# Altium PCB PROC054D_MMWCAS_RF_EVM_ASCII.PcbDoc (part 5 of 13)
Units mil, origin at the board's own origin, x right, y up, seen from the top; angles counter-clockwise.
Board outline 6299.21 x 5370.07 mil, 8 copper layers (L1 TOP, L2 GND, L3 SIGNAL 1, L4 GND, L5 SIGNAL 2, L6 SIGNAL 3, L7 GND, L8 BOTTOM), stack 53.5 mil thick; 775 components, 552 nets, 2648 pads, 7845 vias.
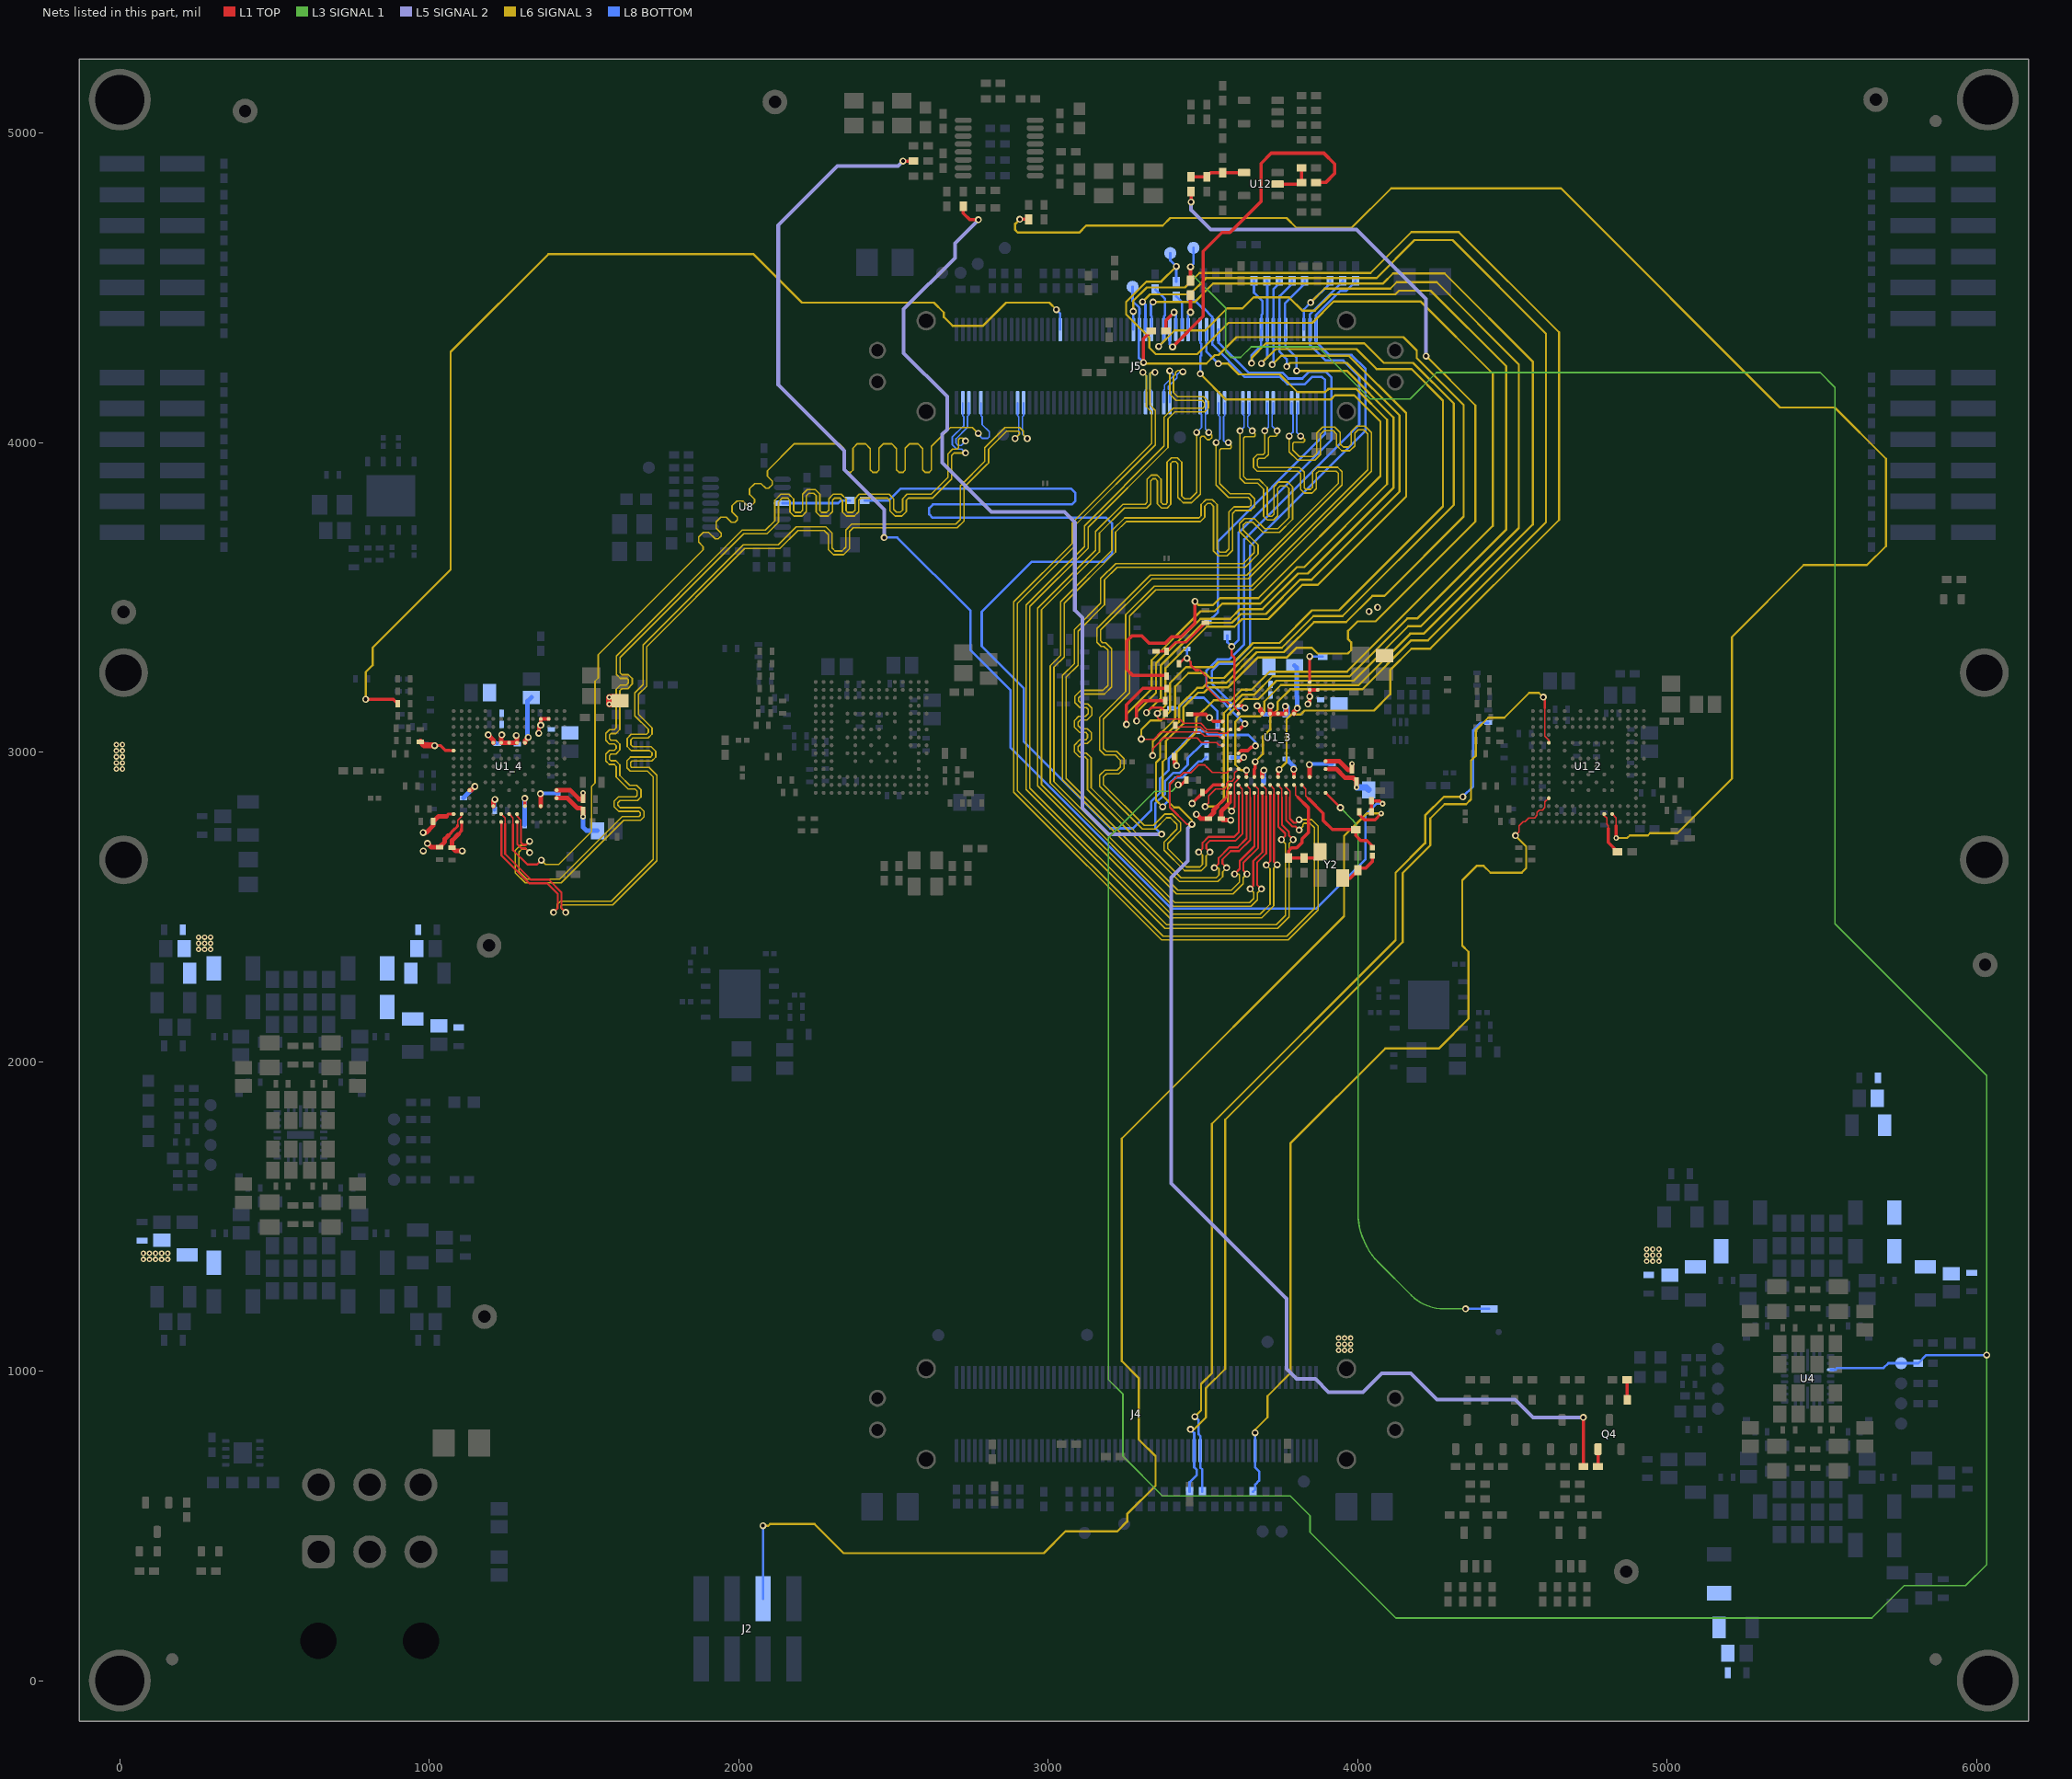
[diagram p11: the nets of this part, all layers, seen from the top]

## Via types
v1: diameter 15.74, hole 5.9, L1 TOP to L2 GND, tented both sides, 5522 vias
v2: diameter 22.4, hole 12.2, L1 TOP to L8 BOTTOM, tented both sides, 1522 vias
v3: diameter 18, hole 8, L1 TOP to L8 BOTTOM, tented both sides, 727 vias
v4: diameter 18, hole 7.87, L1 TOP to L8 BOTTOM, tented top, 50 vias
v5: diameter 24, hole 12, L1 TOP to L8 BOTTOM, tented both sides, 13 vias
v6: diameter 19.68, hole 7.87, L1 TOP to L8 BOTTOM, tented top, 10 vias
v7: diameter 15.74, hole 5.9, L1 TOP to L2 GND, tented top, 1 vias

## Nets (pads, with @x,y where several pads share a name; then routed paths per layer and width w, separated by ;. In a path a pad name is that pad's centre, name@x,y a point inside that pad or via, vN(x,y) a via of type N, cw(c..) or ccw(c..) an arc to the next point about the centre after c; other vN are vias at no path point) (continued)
AWR_2_UART_RX: J4.100 R179_2.1 U1_2.N5 | length 3336.1
  L1 TOP w4: 4605,3142.12 4605,3051 4606,3050 4606,3049.9 4617.94,3037.96 U1_2.N5@4617.94,3030.27
  L1 TOP w8: v2(4600,3177.36) 4605,3172.36 4605,3142.12
  L6 SIGNAL 3 w6.9: v2(3460,812) 3472,812 3509.9,849.9 3509.9,945.07 3571.9,1007.07 3571.9,1812.47 4145.41,2385.97 4145.41,2608.91 4235.1,2698.6 4235.1,2785.63 4280.89,2831.42 4350.77,2831.42 4366.51,2847.16 4366.51,2972.86 4381.71,2988.06 4381.71,3070.64 4422.44,3111.36 4474.45,3111.36 4554.59,3191.51 4585.85,3191.51 v2(4600,3177.36)
  L8 BOTTOM w7.75: R179_2.1@3457,610.42 3457,641.1 3479.46,663.56 3479.46,681.54 3471.93,689.07 3471.93,800.07 v2(3460,812)
AWR_2_UART_TX: J4.101 R11_2.1 R178_2.1 | length 2937.4
  L6 SIGNAL 3 w6.9: v2(3474,853) 3494.15,873.15 3494.15,958.34 3528.87,993.06 3528.87,1798.87 4122.88,2392.87 4122.88,2610.47 4218.18,2705.77 4218.18,2795.22 4278.49,2855.54 v2(4339.79,2855.54)
  L8 BOTTOM w7.75: v2(3474,853) 3486,841 3486,796 3491.61,790.39 3491.61,688.74 3498,682.35 R178_2.1@3498,610.42 ; v2(4339.79,2855.54) 4373.35,2889.1 4373.35,3070.72 4397.63,3095 R11_2.1@4422.06,3095
AWR_2_WARM_RST: J4.110 R174_2.1 U1_2.N12 | length 2930.5
  L1 TOP w4: v2(4510,2730) 4522,2742 4522,2762 4535,2775 4541,2775 4553.46,2787.46 4571.94,2787.46 4579.85,2795.37 4579.85,2805.14 4587.17,2812.46 4596.94,2812.46 4605.44,2820.96 4605.44,2838.64 U1_2.N12@4617.94,2851.13
  L6 SIGNAL 3 w6.9: v2(3668.78,801) 3668.78,810.73 3708.84,850.79 3708.84,919.47 3782.81,993.44 3782.81,1736.06 4088.99,2042.24 4262.01,2042.24 4358.04,2138.27 4358.04,2354.55 4338.18,2374.4 4338.18,2586.12 4384.3,2632.24 4407.51,2632.24 4429.42,2610.34 4530.22,2610.34 4544.96,2625.08 4544.96,2695.04 v2(4510,2730)
  L8 BOTTOM w7.75: R174_2.1@3662,610.42 3668.78,617.2 3668.78,633.76 3681.55,646.53 3681.55,675.72 3668.78,688.49 v2(3668.78,801)
AWR_2_XTAL_CLKM: R129.2 U1_2.F14 | length 139.7
  L1 TOP w4: U1_2.F14@4797.07,2799.95 4797.07,2794.92 4805,2786.99 4805,2767.1 4809.68,2762.42 4809.68,2752.33
  L1 TOP w10.5: 4809.68,2752.33 4809.68,2708.42 R129.2@4840.01,2678.08
AWR_2_XTAL_CLKP: R104.2 U1_2.E14 | length 5230.2
  L1 TOP w4: U1_2.E14@4822.67,2799.95 4835.37,2787.25 4835.37,2762.23
  L1 TOP w10.5: v2(2908.09,4721.32) R104.2@2936.49,4721.32 ; v3(4835.37,2722.31) 4835.37,2762.23
  L6 SIGNAL 3 w6.9: v2(2908.09,4721.32) 2893.5,4706.73 2893.5,4686.9 2901.88,4678.51 3100.48,4678.51 3122.83,4700.86 3369.77,4700.86 3394.77,4725.86 3770.26,4725.86 3802.31,4693.81 3980.44,4693.81 4108.32,4821.69 4657.41,4821.69 5365.44,4113.65 5541.51,4113.65 5707.57,3947.59 5707.57,3665.65 5646.12,3604.2 5441.75,3604.2 5209.7,3372.15 5209.7,2914.51 5033.49,2738.29 4945.21,2738.29 4937.88,2730.96 4879.58,2730.96 4870.93,2722.31 v3(4835.37,2722.31)
AWR_3_1V0_RF1_FILT: C87.1 C88.1 C91.1 C136_3.1 C137_3.1 C138_3.1 C139_3.1 L23.2 U1_3.G5 U1_3.H5 U1_3.J5 | length 127.1
  L1 TOP w15: v2(3719.09,3149.57) 3717.3,3147.78 U1_3.J5@3717.3,3124.27 U1_3.G5@3768.48,3124.27 3768.48,3140.51 3766.34,3142.65 v2(3766.34,3147.83)
  L8 BOTTOM w22: v2(3766.34,3147.83) 3769.38,3144.79 C136_3.1@3769.38,3123.65
AWR_3_1V0_RF2_FILT: C93.1 C140_3.1 C141_3.1 C204.1 C207.1 L24.2 R188_3.2 U1_3.C2 U1_3.D2 | length 74.2
  L1 TOP w12: v2(3839,3155) 3845.25,3161.25 U1_3.D2@3845.26,3201.04 U1_3.C2@3870.85,3201.04
  other v2: 3845.24,3179.65 4037.03,3454.24 4064.35,3467.78
AWR_3_1V2_FILT: C142_3.1 C143_3.1 C144_3.1 C145_3.1 C146_3.1 C147_3.1 C154.1 C155.1 C156.1 L19.2 U1_3.F13 U1_3.N11 U1_3.P14 U1_3.P15 U1_3.R6 U1_3.R14 | length 678.8
  L1 TOP w4: 3576.5,2857.69 3576.5,2873.5 3589.35,2886.35 U1_3.P14@3589.35,2893.95
  L1 TOP w8: 3568.43,2846.28 3576.5,2854.35 3576.5,2857.69 ; 3589.35,2845.01 U1_3.P15@3589.35,2868.36
  L1 TOP w10: v2(3465,2834) 3498.58,2867.58 C146_3.1@3498.58,2870 3509.97,2870 3533.93,2893.96 U1_3.R14@3563.76,2893.95 ; v2(3521.08,3111.07) 3533.48,3098.68 U1_3.R6@3563.76,3098.68 ; 3545.75,2823.6 3568.43,2846.28 ; 3579.25,2828.86 3589.35,2838.95 3589.35,2845.01 ; U1_3.N11@3614.94,2970.72 3620.02,2970.73 v2(3632.19,2982.9)
  L1 TOP w12: C142_3.1@3457.49,3122.71 3509.45,3122.71 v2(3521.08,3111.07) ; v2(3793.51,2944.72) 3793.51,2937.18 3794.07,2936.62 U1_3.F13@3794.07,2919.55
  L1 TOP w15: v2(3479,2798.99) 3492.42,2785.57 C147_3.1@3518,2785.58 ; C147_3.1@3518,2787 3535,2804 3535,2812.85 3545.75,2823.6 ; 3579.25,2828.86 3559,2808.6 C143_3.1@3559,2785.58 3564.59,2779.99 v2(3590,2779.99)
  L8 BOTTOM w12: C145_3.1@3595.75,2982.9 v2(3632.19,2982.9)
  L8 BOTTOM w15: C144_3.1@3769.06,2978.27 3793.51,2953.82 v2(3793.51,2944.72)
  other v3: 3938.25,1067.33 3957.94,1067.33 3977.62,1067.33 3938.25,1087.02 3957.94,1087.02 3977.62,1087.02 3938.25,1106.7 3957.94,1106.7 3977.62,1106.7
AWR_3_1V8_FILT: C128_3.1 C129_3.1 C130_3.1 C131_3.1 C132_3.1 C133_3.1 C134_3.1 C135_3.1 C158.1 C159.1 C160.1 L22.2 U1_3.B11 U1_3.B12 U1_3.D13 U1_3.F5 U1_3.K5 U1_3.K13 | length 707.4
  L1 TOP w12: U1_3.B12@3896.44,2945.13 3905.67,2945.13
  L1 TOP w15: v2(3675.39,3149.45) 3686.19,3138.65 3686.19,3132.45 3691.71,3126.93 U1_3.K5@3691.71,3124.27 ; U1_3.K13@3691.71,2919.55 3691.71,2935.82 v2(3697.03,2941.14) ; U1_3.F5@3794.07,3124.27 3794.07,3130.78 v2(3804.99,3141.7) ; v2(3844,2959.6) 3845.25,2958.35 U1_3.D13@3845.25,2919.55 ; U1_3.B11@3896.44,2970.72 3940.64,2970.72 3969.35,2942.02 C132_3.1@3981.84,2942.02 v3(3981.84,2962.39) ; 3905.67,2945.13 3931.49,2945.13 3959.9,2916.72 3986.18,2916.72 C131_3.1@3996.84,2906.06 v3(3996.84,2885.69)
  L8 BOTTOM w12: v2(3844,2959.6) 3846.4,2962 C134_3.1@3918.09,2962
  L8 BOTTOM w15: v2(3675.39,3149.45) 3703.15,3121.69 C128_3.1@3704.89,3121.69 ; C135_3.1@3696.3,2906 3696.3,2940.41 v2(3697.03,2941.14) ; C130_3.1@3796.42,3279.39 3802.72,3273.09 C129_3.1@3802.72,3216.01 3802.72,3182.09 3804.99,3179.82 v2(3804.99,3141.7)
  L8 BOTTOM w20: v3(3996.84,2885.69) 4028.07,2885.69 C133_3.1@4035.5,2878.26
  other v3: 4934.19,1354.8 4953.87,1354.8 4973.56,1354.8 4934.19,1374.48 4953.87,1374.48 4973.56,1374.48 4934.19,1394.17 4953.87,1394.17 4973.56,1394.17
AWR_3_BSS_LOGGER: J5.41 R14_3.1 | length 2321.9
  L1 TOP w10.5: R14_3.1@3385.09,3246 3382.69,3248.4 3272.6,3248.4 3254,3267 3254,3358.89 3270.08,3374.97 3303.03,3374.97 3326.71,3351.29 3377.1,3351.29 3398.81,3373 3430,3373 3474.73,3417.73 v2(3474.73,3487.05)
  L6 SIGNAL 3 w6.9: v2(3474.73,3487.05) 3487.02,3474.76 3532.33,3474.76 3555.14,3497.57 3679.24,3497.57 4073.72,3892.06 4073.72,4068.11 3988.9,4152.93 3926.62,4152.93 3912.78,4139.09 3574.52,4139.09 v2(3491.61,4222)
  L8 BOTTOM w7.75: v2(3491.61,4222) 3491.61,4278.61 3495,4282 3495,4319 3491.61,4322.39 J5.41@3491.61,4365.06
AWR_3_CSI2_CLK_N: J5.101 U1_3.J14 | length 3367.5
  L1 TOP w4: U1_3.J14@3717.3,2893.95 3729.89,2881.36 3729.89,2862.67
  L1 TOP w6.5: 3729.89,2862.67 3729.89,2646.1 v2(3740,2635.99)
  L6 SIGNAL 3 w5: v2(3479.61,4033) 3479.61,3838.77 3458.84,3818 3440.98,3818 3431.49,3827.49 3431.49,3936.59 3417.53,3950.56 3397.89,3950.56 3384.24,3936.91 3384.24,3805.24 3380,3801 3371.21,3801 3364.99,3807.22 3364.99,3881.76 3351.75,3895 3332.98,3895 3319.74,3881.76 3319.74,3807.21 3313.53,3801 3241.63,3801 3153.51,3712.88 3153.51,3652.05 2966.23,3464.78 2966.23,2891.06 3392.4,2464.89 3690.12,2464.89 3729,2503.77 3729,2624.99 ; 3729,2625 v2(3740,2635.99) 3729,2624.99
  L8 BOTTOM w5.25: v2(3479.61,4033) 3496,4049.39 3496,4090.01 3491.61,4094.4 J5.101@3491.61,4128.84
AWR_3_CSI2_CLK_P: J5.102 U1_3.J15 | length 3330.6
  L1 TOP w6.5: v2(3705,2634.99) 3717.89,2647.88 3717.89,2867.77 U1_3.J15@3717.3,2868.36
  L6 SIGNAL 3 w5: v2(3519,4033) 3528.89,4023.11 3528.89,4016.33 3521.8,4009.24 3514.43,4009.24 3503.47,4020.2 3496.02,4020.2 3491.61,4015.79 3491.61,3833.8 3463.81,3806 3436.01,3806 3419.49,3822.52 3419.49,3931.62 3412.56,3938.56 3402.86,3938.56 3396.24,3931.94 3396.24,3800.27 3384.97,3789 3366.24,3789 3352.99,3802.25 3352.99,3876.79 3346.78,3883 3337.95,3883 3331.74,3876.79 3331.74,3802.24 3318.5,3789 3246.6,3789 3165.51,3707.91 3165.51,3647.08 2978.23,3459.81 2978.23,2896.03 3397.38,2476.89 3685.15,2476.89 3717,2508.74 3717,2623 v2(3705,2634.99)
  L8 BOTTOM w5.25: J5.102@3511.3,4128.84 3511.3,4094.3 3508,4091 3508,4044 v2(3519,4033)
AWR_3_CSI2_TX0_N: J5.92 U1_3.G14 | length 3373.1
  L1 TOP w4: U1_3.G14@3768.48,2893.95 3768.48,2886.51 3781.07,2873.92 3781.07,2853.99
  L1 TOP w6.5: 3781.07,2853.99 3781.07,2784.92 3794.35,2771.64 3800.85,2771.64 v2(3811,2781.79)
  L6 SIGNAL 3 w5: v2(3306,4227) 3317.21,4215.79 3317.21,4116.44 3334.53,4099.11 3334.53,3997.27 3078,3740.74 3078,3674.44 2888.71,3485.15 2888.71,2870.62 3366.21,2393.11 3775.75,2393.11 3872.33,2489.69 3872.33,2760.91 3851.44,2781.8 v2(3811,2781.79)
  L8 BOTTOM w5.25: v2(3306,4227) 3317,4216 3317,4172.22 3314.45,4169.67 J5.92@3314.45,4128.84
AWR_3_CSI2_TX0_P: J5.93 U1_3.G15 | length 3336.4
  L1 TOP w6.5: U1_3.G15@3768.48,2868.36 3769.07,2867.77 3769.07,2779.94 3789.37,2759.64 3799.35,2759.64 v2(3811,2747.99)
  L6 SIGNAL 3 w5: v2(3345.39,4227) 3332.54,4227 3329.21,4223.66 3329.21,4121.41 3346.53,4104.09 3346.53,3992.3 3090,3735.77 3090,3669.47 2900.71,3480.18 2900.71,2875.59 3371.18,2405.11 3770.78,2405.11 3860.33,2494.66 3860.33,2755.94 3846.47,2769.8 3826.79,2769.8 3823.26,2766.27 3823.26,2760.26 v2(3811,2747.99)
  L8 BOTTOM w5.25: J5.93@3334.13,4128.84 3334.13,4168.26 3329,4173.39 3329,4223.46 3332.54,4227 v2(3345.39,4227)
AWR_3_CSI2_TX1_N: J5.95 U1_3.H14 | length 3368.1
  L1 TOP w4: U1_3.H14@3742.89,2893.95 3755.48,2881.36 3755.48,2853.99
  L1 TOP w6.5: 3755.48,2853.99 3755.48,2764.73 3778.01,2742.21 3778.01,2730.67 v2(3791.4,2717.28)
  L6 SIGNAL 3 w5: v2(3393,4232) 3393,4157 3413.53,4136.47 3497.61,4136.47 3505.69,4128.38 3505.69,4116.9 3500.28,4111.49 3404.37,4111.49 3374.97,4082.09 3374.97,3989.13 3117,3731.16 3117,3663.88 2928.7,3475.59 2928.7,2879.14 3377.74,2430.1 3741.81,2430.1 3779,2467.28 3779,2704.87 v2(3791.4,2717.28)
  L8 BOTTOM w5.25: J5.95@3373.5,4128.84 3373.51,4169.81 3376.06,4172.36 3376.06,4186.23 3404.26,4214.43 3404.26,4220.74 v2(3393,4232)
AWR_3_CSI2_TX1_P: J5.96 U1_3.H15 | length 3328.5
  L1 TOP w6.5: U1_3.H15@3742.89,2868.36 3743.48,2867.77 3743.48,2759.75 3766,2737.23 3766,2730.67 ; v2(3754,2717.28) 3766,2729.28
  L6 SIGNAL 3 w5: v2(3435.39,4229) 3431.16,4233.22 3418.37,4233.22 3412.05,4226.9 3412.05,4220.03 3405,4212.98 3405,4161.97 3418.5,4148.47 3502.58,4148.47 3517.69,4133.36 3517.69,4111.93 3505.25,4099.49 3409.34,4099.49 3386.97,4077.12 3386.97,3984.16 3129,3726.19 3129,3658.91 2940.7,3470.62 2940.7,2884.11 3382.71,2442.1 3736.84,2442.1 3767,2472.25 3767,2704.28 v2(3754,2717.28)
  L8 BOTTOM w5.25: J5.96@3393.19,4128.84 3393.19,4167.6 3388.06,4172.73 3388.06,4181.26 3416.26,4209.46 3416.26,4219.35 3425.91,4229 v2(3435.39,4229)
AWR_3_CSI2_TX2_N: J5.104 U1_3.K14 | length 3362.1
  L1 TOP w4: U1_3.K14@3691.71,2893.95 3704.3,2881.36 3704.3,2857.99
  L1 TOP w6.5: v2(3688.96,2557.99) 3675,2571.95 3675,2642.99 3704.3,2672.29 3704.3,2857.99
  L6 SIGNAL 3 w5: v2(3542.61,4000) 3542.61,3862.76 3582.75,3822.62 3646.18,3822.62 3655.4,3813.41 3655.4,3798.04 3649.73,3792.37 3600.36,3792.37 3584,3776.01 3584,3656.87 3573.52,3646.4 3555.18,3646.4 3546,3655.57 3546,3799.96 3530.26,3815.7 3510.15,3815.7 3494.1,3799.65 3494.1,3764.08 3487.02,3757 3247.25,3757 3205.83,3715.57 3205.83,3651.69 3039.78,3485.65 3039.78,3312.51 3006.51,3279.24 3006.51,2899.91 3404.5,2501.91 3655.84,2501.91 3676.34,2522.42 3676.34,2545.38 v2(3688.96,2557.99)
  L8 BOTTOM w5.25: v2(3542.61,4000) 3555,4012.39 3555,4083.99 3550.67,4088.32 J5.104@3550.67,4128.84
AWR_3_CSI2_TX2_P: J5.105 U1_3.K15 | length 3332.1
  L1 TOP w6.5: v2(3652.56,2557.99) 3663,2568.43 3663,2647.97 3692.3,2677.27 3692.3,2867.77 U1_3.K15@3691.71,2868.36
  L6 SIGNAL 3 w5: v2(3582,4000) 3591.34,3990.66 3591.34,3984.02 3588.02,3980.7 3559.16,3980.7 3554.61,3976.15 3554.61,3867.73 3587.72,3834.62 3651.15,3834.62 3667.4,3818.38 3667.4,3793.07 3654.7,3780.37 3605.33,3780.37 3596,3771.04 3596,3651.9 3578.49,3634.4 3550.21,3634.4 3534,3650.6 3534,3794.99 3525.29,3803.7 3515.12,3803.7 3506.1,3794.68 3506.1,3759.11 3491.99,3745 3252.23,3745 3217.83,3710.59 3217.83,3646.71 3051.78,3480.67 3051.78,3307.54 3018.51,3274.27 3018.51,2904.88 3409.47,2513.91 3650.87,2513.91 3664.34,2527.39 3664.34,2546.22 v2(3652.56,2557.99)
  L8 BOTTOM w5.25: J5.105@3570.35,4128.84 3570.35,4087.34 3567,4083.99 3567,4005.57 3569.78,4002.79 3579.21,4002.79 v2(3582,4000)
AWR_3_CSI2_TX3_N: J5.108 U1_3.L14 | length 3356.6
  L1 TOP w4: U1_3.L14@3666.12,2893.95 3678.71,2881.36 3678.71,2859.99
  L1 TOP w6.5: v2(3642.4,2605.99) 3631,2617.39 3631,2642.99 3678.71,2690.7 3678.71,2859.99
  L6 SIGNAL 3 w5: v2(3620,4038) 3620,3885.7 3636.44,3869.27 3676.76,3869.27 3696.24,3849.79 3696.24,3762.06 3708.08,3750.22 3727.93,3750.22 3741.49,3763.78 3741.49,3852.07 3749.95,3860.52 3769.23,3860.52 3778,3851.76 3778,3757.52 3742.07,3721.6 3699.77,3721.6 3666.57,3754.8 3634.65,3754.8 3618.19,3738.35 3618.19,3712.47 3666.2,3664.46 3666.2,3644.66 3630.75,3609.21 3218.03,3609.21 3169.81,3560.99 3169.81,3481.08 3084.43,3395.7 3084.43,3285.75 3046.35,3247.68 3046.35,2910.31 3414.47,2542.18 3597.18,2542.18 3630,2575 3630,2593.6 v2(3642.4,2605.99)
  L8 BOTTOM w5.25: v2(3620,4038) 3621,4038 3633,4050 3633,4087 3629.41,4090.59 J5.108@3629.41,4128.84
AWR_3_CSI2_TX3_P: J5.109 U1_3.L15 | length 3334.2
  L1 TOP w6.5: v2(3602.2,2605.99) 3619,2622.79 3619,2647.97 3666.71,2695.68 3666.71,2867.77 U1_3.L15@3666.12,2868.36
  L6 SIGNAL 3 w5: v2(3602.2,2605.99) 3614.86,2606 3618,2602.86 3618,2579.98 3592.2,2554.18 3419.45,2554.18 3058.35,2915.29 3058.35,3242.71 3096.43,3280.78 3096.43,3390.73 3181.81,3476.11 3181.81,3556.02 3223,3597.21 3635.72,3597.21 3678.2,3639.69 3678.2,3669.44 3630.19,3717.44 3630.19,3733.38 3639.62,3742.8 3661.6,3742.8 3694.8,3709.6 3747.04,3709.6 3790,3752.55 3790,3856.73 3774.2,3872.52 3744.98,3872.52 3729.49,3857.04 3729.49,3768.75 3722.96,3762.22 3713.05,3762.22 3708.24,3767.03 3708.24,3854.76 3681.73,3881.27 3641.41,3881.27 3632,3890.68 3632,4014.25 3636.42,4018.67 3665.39,4018.67 3668.64,4021.92 3668.64,4028.75 v2(3659.39,4038)
  L8 BOTTOM w5.25: J5.109@3649.09,4128.84 3650,4127.93 3650,4089 3645,4084 3645,4052.39 v2(3659.39,4038)
AWR_3_DIG_SYNCIN: R134.2 R185_3.2 U1_3.N10 | length 4055.5
  L1 TOP w10.5: U1_3.N10@3614.94,2996.31 3623.48,3004.85 3644.69,3004.85 3655.16,3015.32 3664.77,3015.32 v2(3669.59,3020.14)
  L8 BOTTOM w7.75: R134.2@2406.54,3813.05 2485.5,3813.05 2523.92,3851.47 3073.92,3851.47 3087.39,3837.99 3087.39,3810.8 3076.84,3800.24 2627.43,3800.24 2615.41,3788.22 2615.41,3768.72 2626.89,3757.25 3187.8,3757.25 3206.05,3738.99 3206.05,3641.46 3179.08,3614.49 2946.04,3614.49 2785.15,3453.59 2785.15,3342.4 2920.89,3206.66 2920.89,3034.08 3201.19,2753.78 3274.73,2753.78 3332.87,2811.91 3332.87,2840.39 3361.14,2868.66 3361.14,2914.18 3389.62,2942.67 3389.62,2979.17 3476.99,3066.54 R185_3.2@3482.96,3066.54 3507.45,3066.54 3518.63,3055.36 3646.87,3055.36 3669.59,3032.65 v2(3669.59,3020.14)
AWR_3_DIG_SYNCIN_RS: R134.1 U8.12 | length 221.8
  L8 BOTTOM w7.75: U8.12@2141.18,3804.18 2321.49,3804.18 2330.36,3813.05 R134.1@2359.3,3813.05
AWR_3_DIG_SYNCOUT: R1_3.1 R157.1 TP1_3.1 | length 3695.6
  L1 TOP w10.5: R1_3.1@3406.9,2985 3406.9,2964.1 v2(3415,2956)
  L6 SIGNAL 3 w6.9: v2(3414,4569.13) 3365.18,4520.31 3317.76,4520.31 3251.71,4454.26 3251.71,4414.13 3326.89,4338.95 3326.89,4306.54 3347.77,4285.66 3481.8,4285.66 3582.85,4386.71 3853.45,4386.71 3923.02,4456.27 4203.36,4456.27 4437.13,4222.49 4437.13,3731.13 3965.58,3259.58 3715.28,3259.58 3657.01,3201.31 3624.36,3201.31 3590.29,3167.23 3535.06,3167.23 3478.11,3110.28 3478.11,3063.91 3415,3000.8 v2(3415,2956)
  L8 BOTTOM w7.75: TP1_3.1@3394.61,4611.81 3394.61,4588.52 v2(3414,4569.13) R157.1@3414,4519.67
AWR_3_FMCW_CLKOUT: J3.1 U1_3.B15 | length 1988.6
  L1 TOP w8.4: U1_3.B15@3896.44,2868.36 v5(3943.9,2820.9)
  L3 SIGNAL 1 w5: v5@3944.09,2820.9 v5(3943.9,2820.9) 3983.22,2781.58 cw(c3939.64,2737.99) 4001.28,2737.99 4001.28,1512.06 ccw(c4230.17,1512.06) 4068.32,1350.21 4173.32,1245.21 ccw(c4279.63,1351.52) 4279.63,1201.17 v2(4349.11,1201.17)
  L8 BOTTOM w7.75: v2(4349.11,1201.17) J3.1@4424.63,1201.17
AWR_3_FMCW_SYNCOUT: R83.1 U1_3.D1 | length 123.8
  L1 TOP w8.4: U1_3.D1@3845.26,3226.63 v2(3845.26,3309)
  L8 BOTTOM w7.75: v2@3845.26,3308.75 R83.1@3886.65,3308.75
AWR_3_GPIO_0: J5.60 R16_3.2 U1_3.N4 | length 1868.9
  L1 TOP w10.5: U1_3.N4@3614.94,3149.86 3628.82,3149.86 v2(3635.99,3142.69)
  L8 BOTTOM w7.75: v2(3635.99,3142.69) 3607.02,3142.69 3528.56,3221.15 3528.56,3261.66 3552.6,3285.7 3596.09,3285.7 3652.58,3342.19 3652.58,3666.6 4025.73,4039.75 4025.73,4237.57 3980.56,4282.74 3909.26,4282.74 3865.63,4326.37 J5.60@3865.63,4365.06 3865.63,4411.67 3944.88,4490.92 3963.46,4490.92 3993,4520.45 R16_3.2@3993,4523
AWR_3_GPIO_1: J5.59 R17_3.2 U1_3.N7 | length 1880.7
  L1 TOP w10.5: U1_3.N7@3614.94,3073.09 3617.38,3073.09 v2(3635.69,3091.4)
  L8 BOTTOM w7.75: v2(3635.69,3091.4) 3511.59,3215.5 3511.59,3263.43 3547.54,3299.38 3584.57,3299.38 3633.58,3348.39 3633.58,3686.92 4005.42,4058.76 4005.42,4213.12 3953.16,4265.37 3896.63,4265.37 3846,4316 3846,4365 J5.59@3845.94,4365.06 3845.94,4414.41 3952,4520.46 R17_3.2@3952,4523
AWR_3_GPIO_2: J5.58 R18_3.2 U1_3.N13 | length 3153.9
  L1 TOP w4: 3602.44,2863 3602.44,2900.5 3614.94,2913 U1_3.N13@3614.94,2919.55
  L1 TOP w6: v2@3593,2816 3596.44,2816 3602.44,2822 3602.44,2863
  L6 SIGNAL 3 w6.9: v2(3593,2809) 3580.14,2821.86 3580.14,3119.16 3632.51,3171.53 3678.83,3171.53 3738.08,3230.78 3987.64,3230.78 4163.73,3406.87 4204.28,3406.87 4521.16,3723.75 4521.16,4252.6 4255.68,4518.08 4126.56,4518.08 4105.91,4497.43 3893.06,4497.43 v2(3847.92,4452.29)
  L8 BOTTOM w7.75: J5.58@3826.26,4365.06 3826.26,4430.63 v2(3847.92,4452.29) 3911,4515.37 R18_3.2@3911,4523
AWR_3_LVDS_FRCLK_N: J5.112 U1_3.M14 | length 3354.6
  L1 TOP w4: U1_3.M14@3640.53,2893.95 3653.12,2881.36 3653.12,2852.99
  L1 TOP w6.5: v2(3576.62,2625.99) 3563,2639.61 3563,2652.99 3590,2679.99 3616.98,2679.99 3653.12,2716.13 3653.12,2852.99
  L6 SIGNAL 3 w5: v2(3576.62,2625.99) 3564,2613.38 3564,2597.91 3548.09,2582 3424.15,2582 3126.83,2879.32 3126.83,2976.49 3118.69,2984.63 3100.19,2984.63 3084.48,3000.33 3084.48,3022.25 3102.04,3039.8 3121.46,3039.8 3127.24,3045.58 3127.24,3057.8 3121.39,3063.65 3101.62,3063.65 3084.41,3080.86 3084.41,3101.64 3098.22,3115.45 3120.39,3115.45 3129.17,3124.23 3129.17,3137.79 3123.08,3143.87 3103.02,3143.87 3086.27,3160.62 3086.27,3180.24 3105.69,3199.66 3177.28,3199.66 3192.82,3215.2 3192.82,3329.22 3180.33,3341.71 3170.85,3341.71 3157.54,3355.02 3157.54,3399.51 3330.26,3572.22 3641.75,3572.22 3937.63,3868.1 3937.63,3901.11 3930.71,3908.03 3874.4,3908.03 3866.56,3900.18 3866.56,3850.66 3852.9,3837 3827.45,3837 3815.45,3849 3815.45,3899.43 3807.18,3907.7 3675.66,3907.7 3663.72,3919.64 3663.72,3949.33 3675.36,3960.97 3694.45,3960.97 3700,3966.52 v2(3700,4038)
  L8 BOTTOM w5.25: v2(3700,4038) 3712,4050 3712,4089.7 3708.15,4093.55 J5.112@3708.15,4128.84
AWR_3_LVDS_FRCLK_P: J5.113 U1_3.M15 | length 3316.7
  L1 TOP w6.5: v2(3537,2625.99) 3551,2639.99 3551,2657.97 3585.02,2691.99 3612,2691.99 3641.12,2721.11 3641.12,2867.77 U1_3.M15@3640.53,2868.36
  L6 SIGNAL 3 w5: v2(3537,2625.99) 3549.42,2626 3552,2623.42 3552,2602.89 3543.11,2594 3429.13,2594 3138.83,2884.29 3138.83,2981.46 3123.66,2996.63 3105.16,2996.63 3096.48,3005.31 3096.48,3017.27 3107.01,3027.8 3126.44,3027.8 3139.25,3040.61 3139.25,3062.77 3126.36,3075.66 3106.6,3075.66 3096.42,3085.83 3096.42,3096.67 3103.2,3103.44 3125.36,3103.44 3141.18,3119.26 3141.18,3142.76 3128.06,3155.88 3107.99,3155.88 3098.28,3165.59 3098.28,3175.27 3110.66,3187.65 3182.25,3187.65 3204.83,3210.22 3204.83,3334.2 3185.3,3353.72 3175.82,3353.72 3169.55,3359.99 3169.55,3394.53 3335.24,3560.22 3646.73,3560.22 3949.63,3863.12 3949.63,3906.08 3935.68,3920.03 3869.43,3920.03 3854.56,3905.16 3854.56,3855.63 3847.93,3849 3832.43,3849 3827.45,3853.98 3827.45,3904.41 3812.16,3919.7 3680.64,3919.7 3675.72,3924.62 3675.72,3944.36 3680.33,3948.97 3699.42,3948.97 3712,3961.55 3712,4015.34 3717.05,4020.4 3736.32,4020.4 3739.39,4023.46 v2(3739.39,4038)
  L8 BOTTOM w5.25: J5.113@3727.83,4128.84 3727.83,4094.68 3724,4090.85 3724,4053.39 v2(3739.39,4038)
AWR_3_LVDS_VALID_N: J5.116 U1_3.N14 | length 3368.5
  L1 TOP w4: U1_3.N14@3614.94,2893.95 3627.53,2881.36 3627.53,2861.88
  L1 TOP w6.5: v2(3522.7,2676.69) 3511,2688.39 3511,2702.01 3522.98,2713.99 3605.98,2713.99 3627.53,2735.54 3627.53,2861.88
  L6 SIGNAL 3 w5: v2(3522.7,2676.69) 3510.37,2664.37 3510.37,2632.43 3494.94,2617 3440.53,2617 3374.35,2683.18 3374.35,2709.34 3416.11,2751.1 3416.11,2766.7 3394.76,2788.04 3382.49,2788.04 3345.8,2751.35 3305.15,2751.35 3166.63,2889.87 3166.63,2924.92 3183.36,2941.65 3223.1,2941.65 3233.54,2952.09 3233.54,2973.56 3216.72,2990.38 3183.26,2990.38 3166.63,3007.01 3166.63,3112.08 3250.64,3196.09 3250.64,3444.23 3342.82,3536.41 3656.88,3536.41 4032.9,3912.42 4032.9,4027.78 4019.1,4041.57 4001.45,4041.57 3991.04,4031.16 3991.04,3989.79 3974.82,3973.57 3948.86,3973.57 3931.89,3990.53 3931.89,4027.29 3921.24,4037.94 3892.11,4037.94 3880,4025.82 3880,3961.11 3861.9,3943.01 3806.1,3943.01 3778.61,3970.5 v2(3778.61,4021)
  L8 BOTTOM w5.25: v2(3778.61,4021) 3791,4033.39 3791,4089.77 3786.89,4093.88 J5.116@3786.89,4128.84
AWR_3_LVDS_VALID_P: J5.117 U1_3.N15 | length 3340.8
  L1 TOP w6.5: v2(3486.3,2676.69) 3499,2689.39 3499,2706.99 3518,2725.99 3601,2725.99 3615.53,2740.52 3615.53,2867.77 U1_3.N15@3614.94,2868.36
  L6 SIGNAL 3 w5: v2(3486.3,2676.69) 3489.04,2676.69 3498.37,2667.36 3498.37,2637.41 3489.96,2629 3445.51,2629 3386.35,2688.16 3386.35,2704.36 3428.11,2746.12 3428.11,2771.68 3399.75,2800.04 3377.51,2800.04 3340.82,2763.35 3310.13,2763.35 3178.64,2894.84 3178.64,2919.94 3188.34,2929.65 3228.07,2929.65 3245.55,2947.12 3245.55,2978.53 3221.69,3002.38 3188.23,3002.38 3178.64,3011.98 3178.64,3107.1 3262.65,3191.11 3262.65,3439.25 3347.8,3524.41 3661.86,3524.41 4044.9,3907.44 4044.9,4032.75 4024.07,4053.57 3996.48,4053.57 3979.04,4036.13 3979.04,3994.76 3969.85,3985.57 3953.83,3985.57 3943.89,3995.5 3943.89,4032.26 3926.22,4049.94 3887.13,4049.94 3868,4030.8 3868,3966.09 3856.92,3955.01 3811.08,3955.01 3790.61,3975.48 3790.61,3997.04 3794.41,4000.83 3825.28,4000.83 3828.62,4004.16 3828.62,4011.11 3818.72,4021 v2(3816,4021)
  L8 BOTTOM w5.25: J5.117@3806.57,4128.84 3806.57,4094.13 3803,4090.56 3803,4034 v2(3816,4021)
AWR_3_MCU_CLKOUT: R5_3.1 R123.1 | length 3152.2
  L1 TOP w10.5: R123.1@2725.57,4763.38 2725.57,4741.34 2746.67,4720.23 v2(2774.74,4720.23)
  L5 SIGNAL 2 w12: v2(2774.74,4720.23) 2698.72,4644.21 2698.72,4596.85 2533.14,4431.28 2533.14,4288.57 2673.22,4148.5 2673.22,4042.73 2657.5,4027.01 2657.5,3934.88 2816.21,3776.18 3052.42,3776.18 3086.24,3742.36 3086.24,3458.76 3110.23,3434.77 3110.23,2819.48 3194.97,2734.74 v2(3366.91,2734.74)
  L8 BOTTOM w7.75: v2(3366.91,2734.74) 3346.25,2755.39 3346.25,2833.24 3377.02,2864.01 3377.02,2905.59 3403.91,2932.48 3424.59,2932.48 3451.15,2959.04 3451.15,2980.73 3496.63,3026.2 R5_3.1@3511.46,3026.2
AWR_3_MSS_LOGGER: J5.42 R15_3.1 | length 2416.3
  L1 TOP w10.5: v2(3252.9,3089.6) 3252.9,3152.72 3306.17,3206 R15_3.1@3382.9,3206
  L6 SIGNAL 3 w6.9: v2(3252.9,3089.6) 3252.9,3122.43 3334.12,3203.65 3334.12,3296.71 3492.7,3455.29 3538.22,3455.29 3562.41,3479.48 3685.5,3479.48 3803.87,3597.85 3827.51,3597.85 4095.39,3865.73 4095.39,4074.36 3996.46,4173.29 3905.45,4173.29 3895.28,4163.11 3805.31,4163.11 3747.91,4220.51 3616.01,4220.51 3581.52,4255 v2(3550,4255)
  L8 BOTTOM w7.75: J5.42@3511.3,4365.06 3511.3,4293.7 v2(3550,4255)
AWR_3_NERROR_IN: R177_3.1 U1_3.P7 | length 193.7
  L1 TOP w4: R177_3.1@3411.4,3086 3416.5,3080.9 3491.68,3080.9 3509.58,3063 3548,3063 3550.41,3060.59 3576.85,3060.59 U1_3.P7@3589.35,3073.09
AWR_3_NERROR_OUT: R9_3.1 R158.1 | length 231.1
  L8 BOTTOM w7.75: R158.1@3396.01,3142 3418.76,3142 3452.56,3175.8 3503.2,3175.8 3547.22,3131.78 R9_3.1@3547.22,3084.16
AWR_3_NRST: R202.2 R211.2 U1_3.P12 | length 7016.6
  L1 TOP w4: 3512.4,2951.6 3530,2934 3556.6,2934 3558,2932.6 3576.81,2932.6 U1_3.P12@3589.35,2945.13
  L1 TOP w6: v2(3464.45,2766.62) 3448.42,2766.62 3393,2822.04 3393,2896.43 3417.57,2921 3425.33,2921 3437.28,2932.94 3460.27,2932.94 3485.93,2958.6 3505.4,2958.6 3512.4,2951.6
  L1 TOP w10.5: v2(3461.75,4777.46) R211.2@3461.75,4811.62 ; R202.2@4729.41,691.84 v2(4729.41,850.2)
  L5 SIGNAL 2 w12: v2(3461.75,4777.46) 3461.75,4751.72 3524.98,4688.48 3996.49,4688.48 4221.28,4463.69 v2(4221.28,4279.76) ; v2(3464.45,2766.62) 3451.08,2753.26 3451.08,2648.47 3397.46,2594.85 3397.46,1606.85 3770.09,1234.22 3770.09,1007.34 3802.5,974.93 3863.42,974.93 3906.05,932.3 4017.58,932.3 4077.68,992.39 4171.37,992.39 4256.22,907.54 4509.63,907.54 4566.97,850.2 v2(4729.41,850.2)
  L6 SIGNAL 3 w6.9: v2(3464.45,2766.62) 3464.45,2779.44 3422.39,2821.5 3407.41,2821.5 3370.09,2858.82 3370.09,2968.16 3380.5,2978.57 3380.5,3035.81 3436.55,3091.87 3436.55,3144.55 3484.26,3192.26 3503.26,3192.26 3520.51,3209.51 3581.65,3209.51 3678.33,3306.18 3772.05,3306.18 3803.18,3337.31 3851.61,3337.31 3870.61,3318.31 3967.86,3318.31 3979.27,3329.72 3979.27,3354.49 3969.36,3364.39 3969.36,3391.95 4000.01,3422.6 4058.17,3422.6 4380.74,3745.17 4380.74,4120.3 v2(4221.28,4279.76)
AWR_3_NRST_HOST: J5.36 R53.1 | length 1156.1
  L1 TOP w10.5: v2(3402,4309) 3501,4408 3501,4618.24 3561.79,4679.04 3587.65,4679.04 3687.59,4778.98 3687.59,4901.64 3721.16,4935.21 3890.87,4935.21 3926.27,4899.81 3926.27,4869.67 3896.82,4840.22 R53.1@3865.5,4840.22
  L8 BOTTOM w7.75: J5.36@3393.19,4365.06 3393.19,4317.81 v2(3402,4309)
AWR_3_NRST_HOST_GS: R53.2 R90.1 U12.2 | length 126.2
  L1 TOP w10.5: U12.2@3741.51,4835.22 3813.25,4835.22 R53.2@3818.25,4840.22 R90.1@3818.25,4887.63
AWR_3_NRST_LED: Q4.1 R202.1 | length 56.1
  L1 TOP w10.5: R202.1@4776.66,691.84 Q4.1@4776.66,747.96
AWR_3_NRST_LED_PW: DS6.1 R200.1 | length 65
  L1 TOP w10.5: DS6.1@4871.15,906.78 R200.1@4871.15,971.8
AWR_3_NRST_RS: C94.1 R37.1 R211.1 U12.4 | length 177.2
  L1 TOP w10.5: R211.1@3461.75,4858.86 R37.1@3512.69,4858.86 3526.45,4872.63 C94.1@3564.27,4872.63 U12.4@3633.24,4872.63
AWR_3_OSC_CLKOUT: R2_3.1 R109.1 R187.1 | length 4262.1
  L1 TOP w10.5: v2(2531.11,4909.65) R109.1@2564.74,4909.65 ; R187.1@4044.71,2807.84 R2_3.1@4044.71,2842.4 4071.46,2842.4 v3(4080.62,2833.24)
  L5 SIGNAL 2 w12: v2(2470.17,3693.31) 2470.17,3783.21 2340.33,3913.05 2340.33,3974.42 2127.73,4187.02 2127.73,4701.89 2319.05,4893.2 2514.66,4893.2 v2(2531.11,4909.65)
  L8 BOTTOM w7.75: v2(2470.17,3693.31) 2512.51,3693.31 2749.2,3456.62 2749.2,3329.21 2878.37,3200.04 2878.37,3014.2 3397.73,2494.84 3866.71,2494.84 4025.02,2653.15 4025.02,2796.23 4062.03,2833.24 v3(4080.62,2833.24)
AWR_3_OSC_CLKOUT_CONN: J2.5 R187.2 | length 4338.5
  L1 TOP w10.5: R187.2@4004.71,2807.84 4004.71,2798.61 4021.79,2781.53 4056.17,2781.53 v3(4076.28,2801.63)
  L6 SIGNAL 3 w6.9: v2(2078.45,500.33) 2095.63,500.33 2101.46,506.16 2244.73,506.16 2338.89,412.01 2985.54,412.01 3055.76,482.23 3223.57,482.23 3255.27,513.94 3255.27,537.94 3346.77,629.44 3346.77,725.4 3292.44,779.72 3292.44,977.68 3237.52,1032.61 3237.52,1751.3 3956.33,2470.11 3956.33,2729 4028.96,2801.63 v3(4076.28,2801.63)
  L8 BOTTOM w7.75: J2.5@2078.45,264.5 v2(2078.45,500.33)
AWR_3_PMIC_CLKOUT: R4_3.1 R81.2 R159.1 TP2_3.1 TP22.1 U4.3 | length 12535.9
  L1 TOP w10.5: v2(3420,2894) 3430,2894 R4_3.1@3446,2910 ; R159.1@3460,4523.59 v2(3460,4568)
  L3 SIGNAL 1 w5.1: v2(3420,2894) 3399.58,2873.58 3344.24,2873.58 3194.43,2723.77 3194.43,972.08 3241.72,924.78 3241.72,724.66 3369.34,597.05 3782.26,597.05 3846.41,532.9 3846.41,479.29 4123.37,202.33 5661.93,202.33 5766.31,306.7 5965.04,306.7 6033.05,374.72 v2(6033.05,1051.92) 6033.05,1954.59 5542.44,2445.2 5542.44,4178.57 5494.58,4226.44 4255.04,4226.44 4169.66,4141.06 4041.1,4141.06 3872.42,4309.74 3656.41,4309.74 3622.11,4275.44 3590.45,4275.44 3573.67,4292.22 3573.67,4434.62 3460,4548.29 v2(3460,4568)
  L8 BOTTOM w7.75: v2(3460,4568) 3469.4,4577.4 TP2_3.1@3469.4,4629.14 ; U4.3@5529.07,1004.63 5544.52,1004.63 5549.81,1009.92 5699.93,1009.92 5715.41,1025.4 TP22.1@5756.51,1025.4 R81.2@5811.76,1025.4 5838.28,1051.92 v2(6033.05,1051.92)
AWR_3_SCL: R102.2 R180_3.1 U1_3.P4 | length 293.1
  L1 TOP w4: 3484.11,3265 3490,3265 3511,3244 3511,3210.53 3558.78,3162.75 3576.46,3162.75 U1_3.P4@3589.35,3149.86
  L1 TOP w8: R180_3.1@3422.91,3286 3440.37,3303.46 v2(3448.24,3303.46) 3460.5,3291.2 3460.5,3281.07 3476.57,3265 3484.11,3265
  L8 BOTTOM w7.75: v2(3448.24,3303.46) R102.2@3448.24,3333.71
AWR_3_SDA: R13_3.1 R112.2 R181_3.1 | length 197.3
  L1 TOP w8: R181_3.1@3349.08,3326 R13_3.1@3382.9,3326 3411.57,3354.67 3444.94,3354.67 R112.2@3508.27,3417.99
AWR_3_SOP0_TDO: J5.37 R155.2 | length 129.5
  L1 TOP w10.5: R155.2@3380.34,4360.87 3380.34,4394.34 v2(3407,4421)
  L8 BOTTOM w7.75: v2(3407,4421) 3412.87,4415.13 J5.37@3412.87,4365.06
AWR_3_SOP1_SYNCOUT: J5.38 R157.2 | length 115.1
  L8 BOTTOM w7.75: R157.2@3414,4472.42 3432.56,4453.87 J5.38@3432.56,4365.06
AWR_3_SOP2_PMICCLKOUT: J5.39 R159.2 | length 114.5
  L1 TOP w10.5: v2(3460,4421) R159.2@3460,4476.35
  L8 BOTTOM w7.75: J5.39@3452.24,4365.06 3452.24,4413.24 v2(3460,4421)
AWR_3_SPI_CLK1: J5.51 R182_3.2 U1_3.R9 | length 3070.7
  L1 TOP w4: v2(3338,2989) 3338,3009.52 3373.48,3045 3481,3045 3495,3031 3544,3031 3553.09,3021.91 U1_3.R9@3563.76,3021.91
  L6 SIGNAL 3 w6.9: v2(3338,2989) 3338,3034.54 3409.86,3106.4 3409.86,3211.75 3453.45,3255.35 3507.35,3255.35 3523.17,3239.53 3568.53,3239.53 3665.68,3336.68 3754.88,3336.68 3857.5,3439.3 3951.19,3439.3 4310.54,3798.65 4310.54,4126.43 4179.5,4257.47 4084.85,4257.47 4021.91,4320.41 3704.05,4320.41 3657.49,4273.85 v2(3657.49,4256.45)
  L8 BOTTOM w7.75: v2(3657.49,4256.45) 3657.49,4282.83 3688.46,4313.8 J5.51@3688.46,4365.06 3690,4366.6 3690,4413 3693,4416 3693,4456.4 3665,4484.4 R182_3.2@3665,4523
AWR_3_SPI_CS1: J5.53 R175_3.1 U1_3.R7 | length 2476.2
  L1 TOP w4: v2(3353,3125) 3353,3111.09 3358.09,3106 3425,3106 3438.25,3092.75 3493.14,3092.75 3512.81,3073.09 U1_3.R7@3563.76,3073.09
  L6 SIGNAL 3 w6.9: v2(3353,3125) 3378.85,3150.85 3378.85,3271.15 3512.76,3405.05 3601.67,3405.05 3626.64,3430.03 3710.72,3430.03 3821.34,3540.65 3871.46,3540.65 4156.68,3825.86 4156.68,4095.44 3971.55,4280.56 3752.56,4280.56 v2(3724,4252)
  L8 BOTTOM w7.75: v2(3724,4252) 3727.83,4255.83 3727.83,4494.93 3747,4514.09 R175_3.1@3747,4523
AWR_3_SPI_HOST_INTR1: J5.54 R10_3.2 R184_3.2 | length 2243.5
  L1 TOP w8: v2(3317.5,3127.5) 3334.2,3144.2 3365.42,3144.2 3378.91,3130.71 R10_3.2@3378.91,3126
  L6 SIGNAL 3 w6.9: v2(3317.5,3127.5) 3363.67,3173.67 3363.67,3279.48 3501.94,3417.75 3593.98,3417.75 3622.67,3446.44 3703.57,3446.44 3814.49,3557.36 3851.2,3557.36 4135.23,3841.38 4135.23,4088.04 3965.56,4257.7 3782.7,4257.7 v2(3771,4246)
  L8 BOTTOM w7.75: v2(3771,4246) 3771,4270 3747.52,4293.48 3747.52,4472.99 3788,4513.46 R184_3.2@3788,4523
AWR_3_SPI_MISO1: J5.55 R12_3.2 R176_3.1 | length 2298.1
  L1 TOP w10.5: v2(3286,3100.71) 3286,3145 3307,3166 R12_3.2@3378.89,3166 R12_3.2@3381.09,3166
  L6 SIGNAL 3 w6.9: v2(3286,3100.71) 3286,3129.08 3348.52,3191.59 3348.52,3286.88 3492.26,3430.63 3588.76,3430.63 3620.34,3462.2 3692.66,3462.2 3807.58,3577.12 3838.98,3577.12 4115.61,3853.76 4115.61,4081.59 3965.2,4232 v2(3803,4232)
  L8 BOTTOM w7.75: v2(3803,4232) 3803,4274 3767.2,4309.8 J5.55@3767.2,4365.06 3765,4367.26 3765,4449.69 3829,4513.69 R176_3.1@3829,4523
AWR_3_SPI_MOSI1: J5.52 R183_3.2 U1_3.R8 | length 2930.6
  L1 TOP w4: v2(3301,3042) 3341.83,3042 3364.83,3065 3491,3065 3505,3051 3551,3051 3554.5,3047.5 U1_3.R8@3563.76,3047.5
  L6 SIGNAL 3 w6.9: v2(3301,3042) 3301,3072.72 3330.67,3102.39 3364.69,3102.39 3393.85,3131.55 3393.85,3223.16 3445.41,3274.71 3533.95,3274.71 3550.77,3291.53 3600.73,3291.53 3662.05,3352.84 3747.2,3352.84 3852.35,3457.99 3940.17,3457.99 4275.96,3793.78 4275.96,4135.88 4174.59,4237.25 4061.49,4237.25 3996.38,4302.36 3735.36,4302.36 v2(3689,4256)
  L8 BOTTOM w7.75: v2(3689,4256) 3708.15,4275.15 3708.15,4520.85 R183_3.2@3706,4523
AWR_3_TCK: J5.33 U1_3.M13 | length 3452.3
  L1 TOP w10.5: U1_3.M13@3640.53,2919.55 3640.53,2938.23 3641.04,2938.74 v2(3641.04,2941.5)
  L6 SIGNAL 3 w6.9: v2(3339,4454) 3473.42,4454 3533.76,4514.34 4082.2,4514.34 4114.3,4546.44 4281.2,4546.44 4565.9,4261.74 4565.9,3734.93 4213.69,3382.72 4169.86,3382.72 4003.86,3216.72 3751.74,3216.72 3698.16,3163.14 3698.16,3128.01 3685.69,3115.54 3622.04,3115.54 3605.1,3098.59 3605.1,2959.44 3623.04,2941.5 v2(3641.04,2941.5)
  L8 BOTTOM w7.75: J5.33@3334.13,4365.06 3334.13,4408.87 3332,4411 3332,4447 v2(3339,4454)
AWR_3_TDI: J5.30 U1_3.H13 | length 3692.2
  L1 TOP w10.5: U1_3.H13@3742.89,2919.55 3742.89,2935.79 3746.6,2939.5 v2(3746.6,2943.69)
  L6 SIGNAL 3 w6.9: v2(3275.08,4424) 3275.08,4458.03 3318.41,4501.36 3442.24,4501.36 3488.85,4547.97 4041.75,4547.97 4174.21,4680.43 4326.7,4680.43 4650.84,4356.29 4650.84,3750.11 4234.5,3333.77 4174.18,3333.77 4105.26,3264.85 4105.26,3186.86 4052.67,3134.26 3828.62,3134.26 3815.55,3121.19 3785.37,3121.19 3770.72,3106.54 3770.72,2967.81 v2(3746.6,2943.69)
  L8 BOTTOM w7.75: J5.30@3275.08,4365.06 v2(3275.08,4424)
AWR_3_TDO: J5.31 R8_3.2 R155.1 TP3_3.1 | length 3689.8
  L1 TOP w10.5: v2(3308.08,4258.64) 3308.08,4335.85 R155.1@3333.1,4360.87
  L6 SIGNAL 3 w6.9: v2(3308.08,4258.64) 3311.36,4255.37 3511.16,4255.37 3538.6,4282.8 3551.01,4282.8 3608.94,4340.72 4148.17,4340.72 4191.07,4297.82 4191.07,4273.28 4342.76,4121.59 4342.76,3760.85 4086.47,3504.55 4047.56,3504.55 3963.07,3420.06 3859.32,3420.06 3761.91,3322.65 3674.21,3322.65 3575.46,3223.91 3515,3223.91 3498.45,3207.36 3481.5,3207.36 3423.22,3149.08 3423.22,3097.79 3361.72,3036.3 3361.72,2979.3 3348.56,2966.14 3348.56,2844.44 v2(3370,2823)
  L8 BOTTOM w7.75: TP3_3.1@3272.86,4503.14 3272.86,4457.09 3294.76,4435.18 3294.76,4432.71 3295.15,4432.32 3295.15,4415.68 3294.76,4415.29 J5.31@3294.76,4365.06 3293,4363.3 3293,4273.73 v2(3308.08,4258.64) ; v2(3370,2823) 3392.32,2845.32 3392.32,2899.28 3410.65,2917.61 3433.64,2917.61 3485.91,2969.89 3496.14,2969.89 R8_3.2@3511.46,2985.2
AWR_3_TMS: J5.32 U1_3.L13 | length 3596.6
  L1 TOP w10.5: U1_3.L13@3666.12,2919.55 3666.12,2944.22 3668.94,2947.04 v2(3668.94,2968.94)
  L6 SIGNAL 3 w6.9: v2(3305,4455) 3328.81,4478.82 3457.67,4478.82 3510.15,4531.3 4060.92,4531.3 4183.77,4654.15 4306.79,4654.15 4608.87,4352.06 4608.87,3742.36 4227.73,3361.22 4173.17,3361.22 4014.8,3202.85 3782.07,3202.85 3741.34,3162.12 3741.34,3137.46 3717.35,3113.47 3717.35,3072.81 3693.68,3049.15 3693.68,2993.68 v2(3668.94,2968.94)
  L8 BOTTOM w7.75: v2(3305,4455) 3314.45,4445.55 J5.32@3314.45,4365.06
AWR_3_UART_RX: J5.44 R179_3.1 U1_3.N5 | length 1743.2
  L1 TOP w4: 3602.19,3240.55 3602.19,3206.52 3602.06,3206.38 3602.06,3144.84 3614.94,3131.96 U1_3.N5@3614.94,3124.27
  L1 TOP w8: v2(3593,3341) 3593,3313.53 3602.19,3304.34 3602.19,3240.55
  L8 BOTTOM w7.75: J5.44@3550.67,4365.06 3550.67,4322.71 3647.38,4226 3757.12,4226 3776,4207.12 3821.41,4207.12 3843.71,4229.42 3896.36,4229.42 3915.48,4210.3 3915.48,4009.22 3615.58,3709.32 3615.58,3363.58 v2(3593,3341) 3578.91,3355.09 R179_3.1@3578.91,3377.34
AWR_3_UART_TX: J5.43 R11_3.1 R178_3.1 | length 1556.8
  L8 BOTTOM w7.75: R178_3.1@3460,4472.42 3498.72,4433.71 3503.06,4433.71 3530,4406.77 3530,4366.04 J5.43@3530.98,4365.06 3530.98,4316.95 3635.93,4212 3750.03,4212 3773.03,4189 3829.68,4189 3852.81,4212.13 3884.78,4212.13 3895,4201.91 3895,4028.11 3548.46,3681.57 3548.46,3452.81 R11_3.1@3516,3420.34
AWR_3_WARM_RST: J5.35 R174_3.1 U1_3.N12 | length 3762.4
  L1 TOP w4: v2(3507,2824) 3518.45,2835.46 3518.45,2858.46 3541.45,2881.46 3568.94,2881.46 3576.85,2889.37 3576.85,2899.14 3584.17,2906.46 3593.94,2906.46 3602.44,2914.96 3602.44,2932.64 U1_3.N12@3614.94,2945.13
  L6 SIGNAL 3 w6.9: v2(3357,4311) 3408.43,4362.43 3507.21,4362.43 3578.3,4433.51 3627.92,4433.51 3663.89,4469.47 3778.25,4469.47 3821.08,4426.64 3862.08,4426.64 3914.57,4479.13 4121.86,4479.13 4133.87,4491.14 4235.66,4491.14 4480.48,4246.32 4480.48,3719.27 4192.94,3431.73 4160.87,3431.73 3973.74,3244.61 3724.98,3244.61 3666.12,3185.75 3627.5,3185.75 3568,3126.25 3568,2849.28 3542.72,2824 v2(3507,2824)
  L8 BOTTOM w7.75: R174_3.1@3346,4496 3377,4465 3377,4411 3374,4408 3374,4365.56 J5.35@3373.5,4365.06 3373.5,4327.5 v2(3357,4311)
AWR_3_XTAL_CLKM: C174.1 R130.2 U1_3.F14 Y2.1 | length 401.9
  L1 TOP w4: U1_3.F14@3794.07,2893.95 3799,2889.02 3799,2862.03 3806.6,2854.44
  L1 TOP w10.5: 3806.6,2854.44 3840.53,2820.51 3840.53,2739.57 3820.31,2719.35 3820.31,2707.62 3803.13,2690.45 3786.52,2690.45 3776.7,2680.63 R130.2@3776.7,2657.9 C174.1@3826.93,2657.9 3859.19,2657.9 Y2.1@3878.92,2677.63
AWR_3_XTAL_CLKP: R126.2 R127.2 U1_3.E14 | length 352.9
  L1 TOP w4: U1_3.E14@3819.67,2893.95 3832.17,2881.45 3832.17,2858.82 3841.8,2849.18
  L1 TOP w10.5: 3841.8,2849.18 3888.95,2802.04 3888.95,2778.94 3918.32,2749.57 R126.2@3993.94,2749.57 3993.94,2730.18 4009.77,2714.35 4029.62,2714.35 4047.24,2696.74 R127.2@4047.24,2691.29
AWR_3_XTALP_RS: C173.1 R127.1 Y2.3 | length 136.4
  L1 TOP w10.5: Y2.3@3951.75,2592.99 3975.72,2592.99 C173.1@4001.11,2618.38 4008.45,2625.72 4026.44,2625.72 4047.24,2646.52 R127.1@4047.24,2665.31
AWR_4_1V0_RF1_FILT: C30.1 C31.1 C34.1 C136_4.1 C137_4.1 C138_4.1 C139_4.1 L7.2 U1_4.G5 U1_4.H5 U1_4.J5 | length 101.7
  L1 TOP w15: v2(1234.09,3055.57) 1232.3,3053.78 U1_4.J5@1232.3,3030.27 U1_4.G5@1283.48,3030.27 1283.48,3051.69 v2(1281.34,3053.83)
AWR_4_1V0_RF2_FILT: C36.1 C81.1 C89.1 C140_4.1 C141_4.1 L8.2 R188_4.2 U1_4.C2 U1_4.D2 | length 177.1
  L1 TOP w12: v2(1354,3061) 1354,3080.9 v2(1360.25,3087.15) U1_4.D2@1360.26,3107.04 U1_4.C2@1385.85,3107.04
  L1 TOP w20: v3(1581.43,3154.69) v3(1581.43,3177.45) 1605.39,3177.45 R188_4.2@1616.77,3166.07 1605.39,3154.69 v3(1581.43,3154.69)
AWR_4_1V2_FILT: C21.1 C29.1 C78.1 C142_4.1 C143_4.1 C144_4.1 C145_4.1 C146_4.1 C147_4.1 L3.2 U1_4.F13 U1_4.N11 U1_4.P14 U1_4.P15 U1_4.R6 U1_4.R14 | length 746.3
  L1 TOP w4: 1091.5,2763.69 1091.5,2779.5 1104.35,2792.35 U1_4.P14@1104.35,2799.95
  L1 TOP w8: 1083.43,2752.28 1091.5,2760.35 1091.5,2763.69 ; 1104.35,2751.01 U1_4.P15@1104.35,2774.36
  L1 TOP w10: v2(1017,3021) 1037,3021 1052,3006 1065,3006 1066.32,3004.68 U1_4.R6@1078.76,3004.68 ; 1055,2793 1061.96,2799.96 U1_4.R14@1078.76,2799.95 ; 1060.75,2729.6 1083.43,2752.28 ; 1094.25,2734.86 1104.35,2744.95 1104.35,2751.01 ; v2(1308.51,2850.72) 1309.07,2850.16 U1_4.F13@1309.07,2825.55
  L1 TOP w15: v2(980,2740) 990,2740 1012,2762 C146_4.1@1012,2775.58 ; v2(994,2705) 1006,2693 C147_4.1@1033,2693 1050,2710 1050,2718.85 1060.75,2729.6 ; C146_4.1@1013.58,2776 1030.58,2793 1055,2793 ; 1094.25,2734.86 1074,2714.6 C143_4.1@1074,2691.58 1084.85,2680.73 v2(1106.3,2680.73) ; U1_4.N11@1129.94,2876.72 1135.02,2876.73 v2(1147.19,2888.9)
  L1 TOP w20: C142_4.1@971.49,3033.71 983.2,3022 1014,3022 1015,3021 v2(1017,3021)
  L8 BOTTOM w15: C144_4.1@1110.64,2852.35 v2(1147.19,2888.9) ; C145_4.1@1308.51,2765.53 v2(1308.51,2850.72)
  other v2: 980.39,2680.33
  other v3: 75.94,1361.02 95.63,1361.02 115.31,1361.02 135,1361.02 154.68,1361.02 75.94,1380.71 95.63,1380.71 115.31,1380.71 135,1380.71 154.68,1380.71 -11.37,2945.41 8.31,2945.41 -11.37,2965.1 8.31,2965.1 -11.37,2984.78 8.31,2984.78 -11.37,3004.47 8.31,3004.47 -11.37,3024.15 8.31,3024.15
AWR_4_1V8_FILT: C128_4.1 C129_4.1 C130_4.1 C131_4.1 C132_4.1 C133_4.1 C134_4.1 C135_4.1 C150.1 C151.1 C152.1 L6.2 U1_4.B11 U1_4.B12 U1_4.D13 U1_4.F5 U1_4.K5 U1_4.K13 | length 714.1
  L1 TOP w15: v2(1190.39,3055.45) 1206.71,3039.13 U1_4.K5@1206.71,3030.27 ; U1_4.K13@1206.71,2825.55 1206.71,2841.82 v2(1212.03,2847.14) ; U1_4.F5@1309.07,3030.27 1309.07,3036.78 v2(1319.99,3047.7) ; v2(1359,2865.6) 1360.25,2864.35 U1_4.D13@1360.25,2825.55 ; U1_4.B12@1411.44,2851.13 1446.49,2851.13 1478.59,2819.04 1489.87,2819.04 C132_4.1@1496.84,2812.06 v3(1496.84,2791.69) ; U1_4.B11@1411.44,2876.72 1455.64,2876.72 1484.35,2848.02 C131_4.1@1496.84,2848.02 v3(1496.84,2868.39)
  L8 BOTTOM w10: v2(1190.39,3055.45) 1218.15,3027.69 C129_4.1@1219.89,3027.69 ; C135_4.1@1211.3,2812 1211.3,2846.41 v2(1212.03,2847.14)
  L8 BOTTOM w12: v2(1359,2865.6) 1360.4,2867 C134_4.1@1417.23,2867
  L8 BOTTOM w15: v2(1319.99,3047.7) 1317.72,3049.97 C128_4.1@1317.72,3127.01 1317.72,3164.62 C130_4.1@1329.9,3176.8 ; v3(1496.84,2791.69) 1496.84,2757.16 1508.01,2745.99 C133_4.1@1543.58,2745.99
  other v3: 254.07,2362.6 273.75,2362.6 293.44,2362.6 254.07,2382.28 273.75,2382.28 293.44,2382.28 254.07,2401.97 273.75,2401.97 293.44,2401.97
AWR_4_BSS_LOGGER: J5.18 R14_4.1 | length 3649.6
  L1 TOP w10.5: v2(794.4,3170.68) 884.32,3170.68 898,3157 R14_4.1@900.09,3157
  L6 SIGNAL 3 w6.9: v2(794.4,3170.68) 794.4,3258.33 816.63,3280.55 816.63,3337.22 1069.02,3589.61 1069.02,4293.09 1384.6,4608.67 2048.03,4608.67 2204.63,4452.07 2630.6,4452.07 2662.53,4420.14 2662.53,4405.77 2690.67,4377.63 2789.88,4377.63 2864.35,4452.11 3003.89,4452.11 v2(3026.59,4429.41)
  L8 BOTTOM w7.75: v2(3026.59,4429.41) 3038.86,4417.14 J5.18@3038.86,4365.06
AWR_4_CSI2_CLK_N: J5.71 U1_4.J14 | length 3680.6
  L1 TOP w4: U1_4.J14@1232.3,2799.95 1244.89,2787.37 1244.89,2768.68
  L1 TOP w6.5: 1244.89,2768.68 1244.89,2671.09 1327.98,2588 1386,2588 1427.32,2546.68 1427.32,2495.68 v2(1441,2482)
  L6 SIGNAL 3 w5: v2(1441,2482) 1425.28,2497.72 1425.28,2502.42 1429.09,2506.23 1592.87,2506.23 1735.26,2648.62 1735.26,2925.18 1709.89,2950.55 1654.15,2950.55 1650.4,2954.3 1650.4,2967.32 1654.89,2971.8 1719.56,2971.8 1731.68,2983.92 1731.68,3002.26 1716.89,3017.05 1657.69,3017.05 1651.57,3023.17 1651.57,3039.52 1657.36,3045.3 1706.97,3045.3 1719.89,3058.22 1719.89,3078.67 1676.18,3122.39 1676.18,3186.48 1702.45,3212.75 1702.45,3340.87 2019.45,3657.87 2132.82,3657.87 2191.14,3716.19 2276.42,3716.19 2289.9,3702.7 2289.9,3654.43 2306.44,3637.89 2338.67,3637.89 2358.04,3657.26 2358.04,3712.81 2369.78,3724.55 2706.1,3724.55 2728.17,3746.62 2728.17,3855.17 2799.9,3926.9 2807.4,3934.41 2807.4,3978.87 2865.53,4037 2903,4037 2908,4032 2908,4028 v2(2893,4013)
  L8 BOTTOM w5.25: v2(2893,4013) 2904.91,4024.91 2904.91,4083.47 2901.06,4087.32 J5.71@2901.06,4128.84
AWR_4_CSI2_CLK_P: J5.72 U1_4.J15 | length 3688.7
  L1 TOP w6.5: U1_4.J15@1232.3,2774.36 1232.89,2773.78 1232.89,2666.11 1323,2576 1381.02,2576 1415.32,2541.7 1415.32,2495.94 v2(1401.38,2482)
  L6 SIGNAL 3 w5: v2(1401.38,2482) 1413.28,2493.9 1413.28,2507.4 1424.11,2518.23 1587.89,2518.23 1723.26,2653.6 1723.26,2920.2 1704.91,2938.55 1649.17,2938.55 1638.4,2949.32 1638.4,2972.3 1649.91,2983.8 1714.58,2983.8 1719.68,2988.9 1719.68,2997.28 1711.91,3005.05 1652.71,3005.05 1639.57,3018.19 1639.57,3044.5 1652.38,3057.3 1702,3057.3 1707.89,3063.2 1707.89,3073.69 1664.18,3117.41 1664.18,3191.46 1690.45,3217.73 1690.45,3345.85 2014.47,3669.87 2127.85,3669.87 2186.17,3728.19 2281.39,3728.19 2301.9,3707.68 2301.9,3659.4 2311.41,3649.89 2333.7,3649.89 2346.04,3662.23 2346.04,3717.78 2364.81,3736.55 2701.13,3736.55 2716.17,3751.59 2716.17,3860.15 2795.4,3939.38 2795.4,3983.85 2860.55,4049 2907.98,4049 2920,4036.98 2920,4025.39 v2(2932.39,4013)
  L8 BOTTOM w5.25: J5.72@2920.75,4128.84 2920.75,4087.55 2916.91,4083.71 2916.91,4028.48 v2(2932.39,4013)
AWR_4_CSI2_TX0_N: J5.62 U1_4.G14 | length 3700.7
  L1 TOP w4: U1_4.G14@1283.48,2799.95 1283.48,2792.52 1296,2780 1296,2760.68 1296.07,2760.61 1296.07,2760
  L1 TOP w6.5: 1296.07,2760 1296.07,2707.91 1302.98,2701 1313.22,2701 v2(1324,2711.78)
  L6 SIGNAL 3 w5: v2(1324,2711.78) 1310.89,2698.67 1294.31,2698.67 1278,2682.37 1278,2609.67 1310.43,2577.24 1426.03,2577.24 1628.28,2779.49 1682.59,2779.49 1694.18,2791.07 1694.18,2808.66 1682.35,2820.49 1617.04,2820.49 1609.16,2828.37 1609.16,2836.27 1616.41,2843.52 1672.53,2843.52 1683.89,2854.88 1683.89,2879.11 1670,2893 1647.48,2893 1616,2924.48 1616,2959.02 1602.76,2972.26 1586.79,2972.26 1582.21,2976.83 1582.21,2988.71 1587.02,2993.51 1602.76,2993.51 1616,3006.75 1616,3025.52 1602.76,3038.76 1586.79,3038.76 1582.21,3043.33 1582.21,3055.21 1587.02,3060.01 1602.76,3060.01 1616,3073.25 1616,3198.71 1622.22,3204.93 1641.43,3204.93 1655.67,3219.17 1655.67,3237.94 1643.43,3250.18 1622.22,3250.18 1616.2,3256.2 1616.2,3305.35 2016.02,3705.17 2091.27,3705.17 2128.42,3742.32 2128.42,3808.37 2141,3820.94 2157.31,3820.94 2165.71,3812.54 2165.71,3775.18 2178.4,3762.49 2204.55,3762.49 2218.45,3776.39 2218.45,3828.31 2226.48,3836.34 2242.54,3836.34 2250.29,3828.59 2250.29,3775.18 2262.98,3762.49 2289.13,3762.49 2303.03,3776.39 2303.03,3813.81 2310.16,3820.94 2326.47,3820.94 2334.87,3812.54 2334.87,3775.18 2347.57,3762.49 2373.71,3762.49 2387.61,3776.39 2387.61,3813.81 2394.74,3820.94 2480.52,3820.94 2488.93,3812.54 2488.93,3778.86 2504.87,3762.91 2527.35,3762.91 2541.67,3777.23 2541.67,3813.81 2548.8,3820.94 2626.57,3820.94 2688.09,3882.46 2688.09,3958.42 2696.23,3966.57 v2(2733,3966.57)
  L8 BOTTOM w5.25: J5.62@2723.89,4128.84 2723.9,4087.38 2727,4084.28 2727,4054 2690,4017 2690,3993.28 2704.28,3979 2720.57,3979 v2(2733,3966.57)
AWR_4_CSI2_TX0_P: J5.63 U1_4.G15 | length 3667
  L1 TOP w6.5: U1_4.G15@1283.48,2774.36 1284.07,2773.78 1284.07,2702.93 1298,2689 1310.38,2689 v2(1324,2675.38)
  L6 SIGNAL 3 w5: v2(1324,2675.38) 1312.71,2686.67 1299.28,2686.67 1290,2677.4 1290,2614.65 1315.41,2589.24 1421.05,2589.24 1623.3,2791.49 1677.61,2791.49 1682.18,2796.05 1682.18,2803.68 1677.37,2808.49 1612.06,2808.49 1597.16,2823.39 1597.16,2841.25 1611.43,2855.52 1667.55,2855.52 1671.89,2859.86 1671.89,2874.13 1665.02,2881 1642.51,2881 1604,2919.51 1604,2954.04 1597.78,2960.26 1581.81,2960.26 1570.21,2971.85 1570.21,2993.69 1582.04,3005.51 1597.78,3005.51 1604,3011.73 1604,3020.54 1597.78,3026.76 1581.81,3026.76 1570.21,3038.35 1570.21,3060.19 1582.04,3072.01 1597.78,3072.01 1604,3078.23 1604,3203.69 1617.24,3216.93 1636.45,3216.93 1643.67,3224.15 1643.67,3232.96 1638.45,3238.18 1617.24,3238.18 1604.2,3251.22 1604.2,3310.33 2011.04,3717.17 2086.3,3717.17 2116.42,3747.29 2116.42,3813.34 2136.03,3832.94 2162.28,3832.94 2177.71,3817.51 2177.71,3780.15 2183.37,3774.49 2199.58,3774.49 2206.45,3781.36 2206.45,3833.28 2221.51,3848.34 2247.51,3848.34 2262.29,3833.56 2262.29,3780.15 2267.95,3774.49 2284.16,3774.49 2291.03,3781.36 2291.03,3818.78 2305.19,3832.94 2331.44,3832.94 2346.87,3817.51 2346.87,3780.15 2352.54,3774.49 2368.74,3774.49 2375.61,3781.36 2375.61,3818.78 2389.77,3832.94 2485.5,3832.94 2500.93,3817.51 2500.93,3783.83 2509.84,3774.91 2522.38,3774.91 2529.67,3782.2 2529.67,3818.78 2543.83,3832.94 2621.6,3832.94 2676.09,3887.43 2676.09,3963.4 2691.26,3978.57 2706.26,3978.57 2710.65,3982.96 2710.65,4010.16 2715.19,4014.7 2723.3,4014.7 v2(2733,4005)
  L8 BOTTOM w5.25: v2(2733,4005) 2719,3991 2709.26,3991 2702,3998.26 2702,4012.02 2739,4049.02 2739,4084.48 2743.58,4089.06 J5.63@2743.58,4128.84
AWR_4_CSI2_TX1_N: J5.65 U1_4.H14 | length 3691.2
  L1 TOP w4: U1_4.H14@1257.89,2799.95 1270.48,2787.37 1270.48,2766.89
  L1 TOP w6.5: 1270.48,2766.89 1270.48,2683.35 1317.04,2636.79 1348.07,2636.79 v2(1362,2650.72)
  L6 SIGNAL 3 w5: v2(1362,2650.72) 1375.87,2636.85 1418.25,2636.85 1524.71,2743.31 1524.71,2888.95 1535.54,2899.78 1535.54,3229.16 1546,3239.62 1546,3314.95 1884.88,3653.83 1884.88,3664.17 1870.23,3678.82 1870.23,3695.43 1885.14,3710.34 1902.61,3710.34 1923.74,3689.2 1933.84,3689.2 1943.18,3698.54 1943.18,3707.1 1926.73,3723.55 1926.73,3743.76 1941.54,3758.57 1960.11,3758.57 1975.67,3743.01 1988.26,3743.01 1995.71,3750.46 1995.71,3759.35 1978.15,3776.92 1978.15,3795.45 1993.52,3810.83 2013.19,3810.83 2029.2,3794.82 2039.28,3794.82 2051.3,3806.84 2051.3,3816.62 2035.1,3832.82 2035.1,3851.34 2051.53,3867.77 2071.94,3867.77 2087.45,3852.26 2096.42,3852.26 2108.01,3863.84 2108.01,3875.87 2092.98,3890.89 2092.98,3909.54 2179.71,3996.27 2324.85,3996.27 2340.28,3980.84 2340.28,3912.29 2348.42,3904.15 2361.93,3904.15 2369.02,3911.24 2369.02,3982.11 2383.18,3996.27 2409.43,3996.27 2424.86,3980.84 2424.86,3912.29 2433,3904.15 2446.51,3904.15 2453.6,3911.24 2453.6,3982.11 2467.76,3996.27 2494.01,3996.27 2509.44,3980.84 2509.44,3912.29 2517.58,3904.15 2531.09,3904.15 2538.18,3911.24 2538.18,3982.11 2552.34,3996.27 2578.59,3996.27 2594.02,3980.84 2594.02,3912.29 2602.16,3904.15 2615.67,3904.15 2622.76,3911.24 2622.76,3987.55 2684.4,4049.18 2754.75,4049.18 v2(2774,4029.93)
  L8 BOTTOM w5.25: v2@2774,4025.93 2785.93,4014 ; v2@2775.5,4025.93 v2@2775.5,4029.93 ; 2779.97,4019.97 2785.93,4014 ; J5.65@2782.95,4128.84 2782.95,4087.32 2786.8,4083.47 2786.8,4058.2 2810,4035 2810,4019.25 2804.75,4014 2787.43,4014 ; 2796.09,4014 2787.43,4014 ; 2785.93,4014 2787.43,4014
